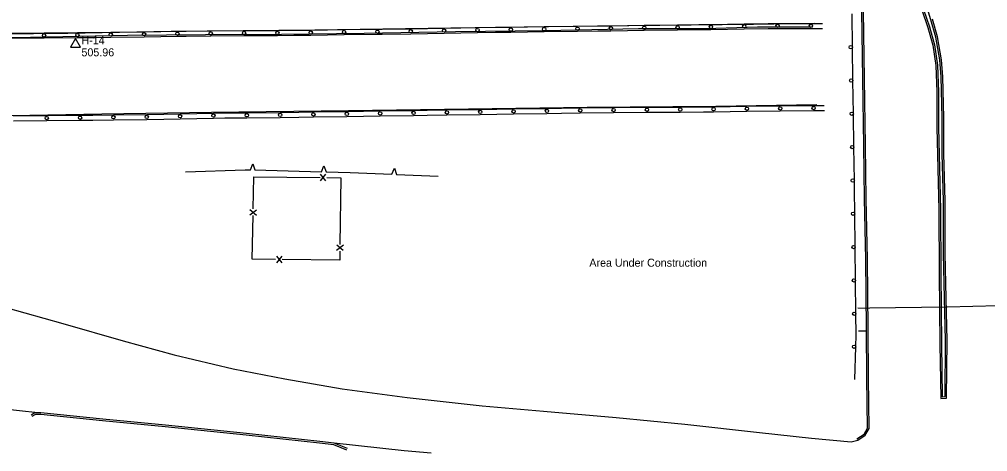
# Model space of a CAD drawing. Extents: x 2402803 to 2427059, y 6985292 to 6997652.
# Drawn here: x 2422158 to 2422739, y 6991224 to 6991483 of the extents above; entities that cross this region are included whole.
import ezdxf

# ---------------------------------------------------------------- set-up
doc = ezdxf.new("R2010")
doc.units = 0
for name, color, linetype in [('p_control ground ctrl', 7, 'Continuous'), ('p_dtm retaining wall', 7, 'Continuous'), ('p_road - paved curb', 7, 'Continuous'), ('p_road bridge end', 7, 'Continuous'), ('p_road conc barrier', 7, 'Continuous'), ('p_road guard rails', 7, 'Continuous'), ('p_structure fence', 7, 'Continuous'), ('p_structure ruins', 7, 'Continuous'), ('p_structure sidewalk', 7, 'Continuous'), ('V7 LEVEL 31', 7, 'Continuous')]:
    doc.layers.add(name, color=color, linetype=linetype)

msp = doc.modelspace()

# ---------------------------------------------------------------- linework, layer by layer
at = {"layer": 'p_control ground ctrl'}
for p, q in [((2422191.74, 6991471.52), (2422188.74, 6991466.32)), ((2422194.74, 6991466.32), (2422191.74, 6991471.52)), ((2422191.74, 6991468.04), (2422191.74, 6991468.08)), ((2422188.74, 6991466.32), (2422194.74, 6991466.32))]:
    msp.add_line(p, q, dxfattribs=at)
at = {"layer": 'p_dtm retaining wall'}
for p, q in [((2422299.36, 6991392.64), (2422339.33, 6991391.56)), ((2422384.24, 6991389.97), (2422409.23, 6991388.96))]:
    msp.add_line(p, q, dxfattribs=at)
for points in [[(2422257.65, 6991391.59), (2422293.51, 6991392.8), (2422296.59, 6991392.72)], [(2422296.59, 6991392.72), (2422298.01, 6991396.31), (2422299.36, 6991392.64)], [(2422339.33, 6991391.56), (2422340.74, 6991395.15), (2422342.09, 6991391.48)], [(2422381.53, 6991390.08), (2422382.99, 6991393.65), (2422384.3, 6991389.97)], [(2422342.09, 6991391.48), (2422356.56, 6991391.09), (2422381.53, 6991390.08)]]:
    msp.add_lwpolyline(points, dxfattribs=at)
at = {"layer": 'p_road - paved curb'}
for points in [[(2422660.37, 6991231.35), (2422664.65, 6991234.18), (2422666.79, 6991237.76), (2422666.35, 6991267.89), (2422666.08, 6991297.42), (2422665.81, 6991339.05), (2422664.87, 6991375.29), (2422664.52, 6991407.41), (2422663.94, 6991447.31), (2422663.4, 6991487.9), (2422662.9, 6991529.87), (2422662.16, 6991569.29), (2422661.76, 6991604.55), (2422661.39, 6991635.63), (2422660.68, 6991673.4), (2422660.1, 6991708.01), (2422659.81, 6991739.54), (2422658.86, 6991759.41), (2422658.88, 6991767.24), (2422657.43, 6991769.93), (2422655.84, 6991771.74)], [(2422660.92, 6991230.52), (2422665.39, 6991233.47), (2422667.79, 6991237.49), (2422667.35, 6991267.9), (2422667.08, 6991297.43), (2422666.81, 6991339.07), (2422665.87, 6991375.31), (2422665.52, 6991407.42), (2422664.94, 6991447.32), (2422664.4, 6991487.91), (2422663.9, 6991529.89), (2422663.16, 6991569.31), (2422662.76, 6991604.56), (2422662.39, 6991635.65), (2422661.68, 6991673.42), (2422661.1, 6991708.02), (2422660.81, 6991739.57), (2422659.86, 6991759.43), (2422659.88, 6991767.49), (2422658.26, 6991770.5), (2422656.59, 6991772.4)], [(2422700.22, 6991488.96), (2422703.84, 6991478.43), (2422706.9, 6991467.77), (2422708.76, 6991455.51), (2422709.28, 6991439.48), (2422709.37, 6991418.16), (2422710.42, 6991368.74), (2422710.63, 6991330.64), (2422711.04, 6991288.12), (2422711.58, 6991256.61), (2422713.2, 6991256.67), (2422713.53, 6991290.4), (2422712.86, 6991315.7), (2422712.36, 6991342.51), (2422712.25, 6991374.15), (2422711.57, 6991402.36), (2422711.46, 6991424.01), (2422710.98, 6991448.55), (2422710.18, 6991458.69), (2422707.74, 6991472.3), (2422704.66, 6991482.82), (2422701.17, 6991494.75)], [(2422699.25, 6991488.71), (2422702.89, 6991478.13), (2422705.92, 6991467.56), (2422707.76, 6991455.42), (2422708.28, 6991439.46), (2422708.37, 6991418.15), (2422709.42, 6991368.73), (2422709.63, 6991330.63), (2422710.04, 6991288.11), (2422710.6, 6991255.58), (2422714.19, 6991255.7), (2422714.53, 6991290.41), (2422713.86, 6991315.72), (2422713.36, 6991342.52), (2422713.25, 6991374.16), (2422712.57, 6991402.37), (2422712.46, 6991424.02), (2422711.98, 6991448.6), (2422711.17, 6991458.82), (2422708.71, 6991472.53), (2422705.62, 6991483.1)], [(2421731.66, 6991469.62), (2421798.31, 6991469.7), (2421875.87, 6991470.84), (2421959.71, 6991471.78), (2422045.53, 6991472.48), (2422104.79, 6991473.88), (2422187.09, 6991474.64), (2422249.13, 6991476.01), (2422335.33, 6991476.81), (2422416.79, 6991477.93), (2422504.89, 6991479.07), (2422598.43, 6991480.18), (2422634.76, 6991480.7)], [(2422633.77, 6991478.23), (2422600.76, 6991478.27), (2422569.47, 6991477.37), (2422529.43, 6991477.3), (2422473.49, 6991476.04), (2422419.7, 6991475.61), (2422364.84, 6991474.51), (2422315.35, 6991473.88), (2422269.63, 6991473.72), (2422222.99, 6991473.38), (2422164.85, 6991472.15), (2422097.27, 6991471.43), (2422044.16, 6991470.23), (2421992.42, 6991469.64), (2421934.88, 6991468.66), (2421882.22, 6991468.38), (2421844.81, 6991467.91), (2421804.41, 6991467.01), (2421732.91, 6991466.08)], [(2421731.79, 6991401.24), (2421788.83, 6991404.21), (2421847.23, 6991406.25), (2421856.78, 6991421.37), (2421923.62, 6991422.35), (2421985.78, 6991423.14), (2422066.1, 6991423.77), (2422142.66, 6991425.08), (2422207.6, 6991426.26), (2422273.25, 6991427.42), (2422355.45, 6991428.42), (2422427.41, 6991429.24), (2422498.6, 6991430.31), (2422575.82, 6991430.85), (2422636.28, 6991431.97)], [(2422149.9, 6991310.18), (2422184.23, 6991300.59), (2422220.32, 6991290.17), (2422250.97, 6991281.79), (2422286.23, 6991273.4), (2422317.27, 6991267.39), (2422351.69, 6991261.29), (2422390.56, 6991256.11), (2422435.61, 6991251.06), (2422472.32, 6991247.99), (2422516.05, 6991244.18), (2422557.24, 6991240.06), (2422601.87, 6991235.06), (2422633.09, 6991231.71), (2422656.95, 6991229.48), (2422660.92, 6991230.52)], [(2422127.01, 6991251.81), (2422171.02, 6991246.98)], [(2422354.93, 6991225.53), (2422346.95, 6991228.71), (2422338.26, 6991229.79), (2422294.2, 6991234.49), (2422245.66, 6991239.54), (2422208.12, 6991243.15), (2422171.02, 6991246.98), (2422167.45, 6991246.89), (2422165.08, 6991245.63)], [(2422354.56, 6991224.6), (2422346.7, 6991227.73), (2422338.15, 6991228.8), (2422294.1, 6991233.5), (2422245.56, 6991238.54), (2422208.02, 6991242.15), (2422170.98, 6991245.98), (2422167.71, 6991245.9), (2422165.55, 6991244.75)], [(2422388.88, 6991224.16), (2422346.92, 6991228.71)], [(2422405.05, 6991222.81), (2422388.88, 6991224.16)]]:
    msp.add_lwpolyline(points, dxfattribs=at)
at = {"layer": 'p_road bridge end'}
msp.add_lwpolyline([(2422660.84, 6991309.94), (2422666.83, 6991309.65), (2422668.13, 6991310.01), (2422714.44, 6991310.62), (2422745.24, 6991311.24), (2422746.12, 6991311.33), (2422751.98, 6991311.63)], dxfattribs=at)
at = {"layer": 'p_road conc barrier'}
for p, q in [((2422512.77, 6991479.14), (2422532.77, 6991479.43)), ((2422532.77, 6991479.43), (2422552.77, 6991479.72)), ((2422572.76, 6991480.02), (2422592.75, 6991480.35)), ((2422612.8, 6991480.59), (2422632.8, 6991480.59)), ((2422632.8, 6991480.59), (2422639.68, 6991480.59)), ((2422152.88, 6991474.7), (2422172.87, 6991474.9)), ((2422172.87, 6991474.9), (2422192.87, 6991475.1)), ((2422212.85, 6991475.34), (2422232.84, 6991475.62)), ((2422232.84, 6991475.62), (2422252.82, 6991475.9)), ((2422272.84, 6991476.1), (2422292.83, 6991476.26)), ((2422292.83, 6991476.26), (2422312.83, 6991476.42)), ((2422292.86, 6991473.26), (2422312.86, 6991473.42)), ((2422332.82, 6991476.62), (2422352.82, 6991476.85)), ((2422332.86, 6991473.62), (2422352.85, 6991473.85)), ((2422352.82, 6991476.85), (2422372.81, 6991477.09)), ((2422352.85, 6991473.85), (2422372.85, 6991474.09)), ((2422392.8, 6991477.41), (2422412.79, 6991477.75)), ((2422392.85, 6991474.41), (2422412.84, 6991474.75)), ((2422412.79, 6991477.75), (2422432.79, 6991478.09)), ((2422412.84, 6991474.75), (2422432.84, 6991475.09)), ((2422452.8, 6991478.38), (2422472.79, 6991478.63)), ((2422452.84, 6991475.38), (2422472.83, 6991475.63)), ((2422472.79, 6991478.63), (2422492.79, 6991478.88)), ((2422472.83, 6991475.63), (2422492.82, 6991475.88)), ((2422512.82, 6991476.14), (2422532.81, 6991476.43)), ((2422532.81, 6991476.43), (2422552.81, 6991476.72)), ((2422572.81, 6991477.02), (2422592.8, 6991477.35)), ((2422612.8, 6991477.59), (2422632.8, 6991477.59)), ((2422632.8, 6991477.59), (2422639.68, 6991477.59)), ((2422152.91, 6991471.7), (2422172.9, 6991471.9)), ((2422172.9, 6991471.9), (2422192.9, 6991472.1)), ((2422212.89, 6991472.34), (2422232.88, 6991472.62)), ((2422232.88, 6991472.62), (2422252.86, 6991472.91)), ((2422272.86, 6991473.1), (2422292.86, 6991473.26)), ((2422294.47, 6991427.02), (2422314.47, 6991427.21)), ((2422334.44, 6991427.45), (2422354.44, 6991427.77)), ((2422354.44, 6991427.77), (2422374.44, 6991428.09)), ((2422374.44, 6991428.09), (2422394.43, 6991428.41)), ((2422414.43, 6991428.72), (2422434.43, 6991429.02)), ((2422434.43, 6991429.02), (2422454.43, 6991429.32)), ((2422454.43, 6991429.32), (2422474.43, 6991429.62)), ((2422494.44, 6991429.86), (2422514.43, 6991430.05)), ((2422494.47, 6991426.86), (2422514.46, 6991427.05)), ((2422514.43, 6991430.05), (2422534.43, 6991430.24)), ((2422514.46, 6991427.05), (2422534.45, 6991427.24)), ((2422534.43, 6991430.24), (2422554.42, 6991430.43)), ((2422534.45, 6991427.24), (2422554.45, 6991427.43)), ((2422574.41, 6991430.63), (2422594.4, 6991430.84)), ((2422574.44, 6991427.63), (2422594.44, 6991427.84)), ((2422594.4, 6991430.84), (2422614.4, 6991431.06)), ((2422594.44, 6991427.84), (2422614.43, 6991428.06)), ((2422614.4, 6991431.06), (2422634.39, 6991431.27)), ((2422614.43, 6991428.06), (2422634.43, 6991428.27)), ((2422634.39, 6991431.27), (2422640.82, 6991431.34)), ((2422634.43, 6991428.27), (2422640.86, 6991428.34)), ((2422154.49, 6991425.12), (2422174.49, 6991425.31)), ((2422154.52, 6991422.12), (2422174.52, 6991422.31)), ((2422174.49, 6991425.31), (2422194.49, 6991425.51)), ((2422174.52, 6991422.31), (2422194.52, 6991422.51)), ((2422214.48, 6991425.75), (2422234.48, 6991426.01)), ((2422214.52, 6991422.75), (2422234.52, 6991423.01)), ((2422254.45, 6991426.34), (2422274.45, 6991426.76)), ((2422254.51, 6991423.34), (2422274.51, 6991423.76)), ((2422294.5, 6991424.02), (2422314.49, 6991424.21)), ((2422334.49, 6991424.45), (2422354.49, 6991424.77)), ((2422354.49, 6991424.77), (2422374.48, 6991425.09)), ((2422374.48, 6991425.09), (2422394.48, 6991425.41)), ((2422414.48, 6991425.72), (2422434.48, 6991426.02)), ((2422434.48, 6991426.02), (2422454.47, 6991426.32)), ((2422454.47, 6991426.32), (2422474.47, 6991426.62))]:
    msp.add_line(p, q, dxfattribs=at)
for points in [[(2422552.77, 6991479.72), (2422565.48, 6991479.9), (2422572.76, 6991480.02)], [(2422592.75, 6991480.35), (2422607.1, 6991480.59), (2422612.8, 6991480.59)], [(2422192.87, 6991475.1), (2422203.68, 6991475.21), (2422212.85, 6991475.34)], [(2422252.82, 6991475.9), (2422258.13, 6991475.98), (2422272.84, 6991476.1)], [(2422312.83, 6991476.42), (2422322.62, 6991476.5), (2422332.82, 6991476.62)], [(2422312.86, 6991473.42), (2422322.65, 6991473.5), (2422332.86, 6991473.62)], [(2422372.81, 6991477.09), (2422375.57, 6991477.12), (2422392.8, 6991477.41)], [(2422372.85, 6991474.09), (2422375.61, 6991474.12), (2422392.85, 6991474.41)], [(2422432.79, 6991478.09), (2422443.61, 6991478.27), (2422452.8, 6991478.38)], [(2422432.84, 6991475.09), (2422443.65, 6991475.27), (2422452.84, 6991475.38)], [(2422492.79, 6991478.88), (2422504.99, 6991479.03), (2422512.77, 6991479.14)], [(2422492.82, 6991475.88), (2422505.03, 6991476.03), (2422512.82, 6991476.14)], [(2422552.81, 6991476.72), (2422565.52, 6991476.9), (2422572.81, 6991477.02)], [(2422592.8, 6991477.35), (2422607.12, 6991477.59), (2422612.8, 6991477.59)], [(2422192.9, 6991472.1), (2422203.72, 6991472.21), (2422212.89, 6991472.34)], [(2422252.86, 6991472.91), (2422258.17, 6991472.98), (2422272.86, 6991473.1)], [(2422274.45, 6991426.76), (2422281.31, 6991426.9), (2422294.47, 6991427.02)], [(2422314.47, 6991427.21), (2422325.7, 6991427.31), (2422334.44, 6991427.45)], [(2422394.43, 6991428.41), (2422402.56, 6991428.54), (2422414.43, 6991428.72)], [(2422474.43, 6991429.62), (2422483.16, 6991429.75), (2422494.44, 6991429.86)], [(2422554.42, 6991430.43), (2422568.25, 6991430.56), (2422574.41, 6991430.63)], [(2422554.45, 6991427.43), (2422568.28, 6991427.56), (2422574.44, 6991427.63)], [(2422194.49, 6991425.51), (2422202.19, 6991425.59), (2422214.48, 6991425.75)], [(2422194.52, 6991422.51), (2422202.23, 6991422.59), (2422214.52, 6991422.75)], [(2422234.48, 6991426.01), (2422244.73, 6991426.14), (2422254.45, 6991426.34)], [(2422234.52, 6991423.01), (2422244.78, 6991423.14), (2422254.51, 6991423.34)], [(2422274.51, 6991423.76), (2422281.35, 6991423.9), (2422294.5, 6991424.02)], [(2422314.49, 6991424.21), (2422325.74, 6991424.31), (2422334.49, 6991424.45)], [(2422394.48, 6991425.41), (2422402.6, 6991425.54), (2422414.48, 6991425.72)], [(2422474.47, 6991426.62), (2422483.2, 6991426.75), (2422494.47, 6991426.86)]]:
    msp.add_lwpolyline(points, dxfattribs=at)
for centre in [(2422552.79, 6991478.22), (2422572.78, 6991478.52), (2422592.78, 6991478.85), (2422612.8, 6991479.09), (2422632.8, 6991479.09), (2422172.89, 6991473.4), (2422192.89, 6991473.6), (2422212.87, 6991473.84), (2422232.86, 6991474.12), (2422252.84, 6991474.4), (2422272.85, 6991474.6), (2422292.85, 6991474.76), (2422312.85, 6991474.92), (2422332.84, 6991475.12), (2422352.83, 6991475.35), (2422372.83, 6991475.59), (2422392.82, 6991475.91), (2422412.82, 6991476.25), (2422432.82, 6991476.59), (2422452.82, 6991476.88), (2422472.81, 6991477.13), (2422492.8, 6991477.38), (2422512.8, 6991477.64), (2422532.79, 6991477.93), (2422334.46, 6991425.95), (2422354.46, 6991426.27), (2422374.46, 6991426.59), (2422394.46, 6991426.91), (2422414.46, 6991427.22), (2422434.45, 6991427.52), (2422454.45, 6991427.82), (2422474.45, 6991428.12), (2422494.45, 6991428.36), (2422514.45, 6991428.55), (2422534.44, 6991428.74), (2422554.43, 6991428.93), (2422574.43, 6991429.13), (2422594.42, 6991429.34), (2422614.42, 6991429.56), (2422634.41, 6991429.77), (2422174.51, 6991423.81), (2422194.5, 6991424.01), (2422214.5, 6991424.25), (2422234.5, 6991424.51), (2422254.48, 6991424.84), (2422274.48, 6991425.26), (2422294.49, 6991425.52), (2422314.48, 6991425.71)]:
    msp.add_circle(centre, 1, dxfattribs=at)
at = {"layer": 'p_road guard rails'}
for p, q in [((2422657.72, 6991466.34), (2422657.44, 6991486.34)), ((2422658.01, 6991446.35), (2422657.72, 6991466.34)), ((2422658.29, 6991426.35), (2422658.01, 6991446.35)), ((2422658.58, 6991406.35), (2422658.29, 6991426.35)), ((2422658.86, 6991386.36), (2422658.58, 6991406.35)), ((2422659.33, 6991346.39), (2422659.1, 6991366.37)), ((2422659.56, 6991326.41), (2422659.33, 6991346.39)), ((2422659.79, 6991306.43), (2422659.56, 6991326.41)), ((2422659.09, 6991266.94), (2422659.7, 6991286.57))]:
    msp.add_line(p, q, dxfattribs=at)
for points in [[(2422659.1, 6991366.37), (2422658.94, 6991380.81), (2422658.86, 6991386.36)], [(2422659.7, 6991286.57), (2422659.93, 6991293.78), (2422659.79, 6991306.43)]]:
    msp.add_lwpolyline(points, dxfattribs=at)
for centre in [(2422656.72, 6991466.33), (2422657.01, 6991446.33), (2422657.29, 6991426.34), (2422657.58, 6991406.34), (2422657.86, 6991386.34), (2422658.1, 6991366.36), (2422658.33, 6991346.38), (2422658.56, 6991326.4), (2422658.79, 6991306.42), (2422658.7, 6991286.61)]:
    msp.add_circle(centre, 1, dxfattribs=at)
at = {"layer": 'p_structure fence'}
for p, q in [((2422298.32, 6991369.24), (2422298.68, 6991388.54)), ((2422298.45, 6991388.54), (2422338.44, 6991388.12)), ((2422338.62, 6991386.15), (2422341.86, 6991390.12)), ((2422341.82, 6991386.12), (2422338.66, 6991390.15)), ((2422342.44, 6991388.08), (2422350.96, 6991387.99)), ((2422350.96, 6991387.99), (2422350.35, 6991348)), ((2422300.28, 6991368.61), (2422296.22, 6991365.48)), ((2422300.22, 6991365.41), (2422296.28, 6991368.68)), ((2422348.32, 6991344.63), (2422352.37, 6991347.77)), ((2422348.37, 6991347.83), (2422352.32, 6991344.57)), ((2422315.5, 6991340.92), (2422312.25, 6991336.96)), ((2422312.3, 6991340.96), (2422315.45, 6991336.92))]:
    msp.add_line(p, q, dxfattribs=at)
for points in [[(2422311.67, 6991339), (2422297.77, 6991339.17), (2422298.25, 6991365.25)], [(2422350.28, 6991344), (2422350.2, 6991338.53), (2422315.67, 6991338.95)]]:
    msp.add_lwpolyline(points, dxfattribs=at)
at = {"layer": 'p_structure sidewalk'}
msp.add_lwpolyline([(2422666.09, 6991295.97), (2422661.29, 6991296.02)], dxfattribs=at)

# ---------------------------------------------------------------- texts
at = {"layer": 'p_control ground ctrl'}
msp.add_text('  H-14', height=4.8, dxfattribs=at).set_placement((2422191.74, 6991468.04))
at = {"layer": 'p_structure ruins'}
msp.add_text('Area Under Construction', height=4.8, dxfattribs=at).set_placement((2422499.9, 6991334.61))
at = {"layer": 'V7 LEVEL 31'}
msp.add_text('  505.96', height=4.8, dxfattribs=at).set_placement((2422191.74, 6991460.84))

doc.saveas('drawing.dxf')
